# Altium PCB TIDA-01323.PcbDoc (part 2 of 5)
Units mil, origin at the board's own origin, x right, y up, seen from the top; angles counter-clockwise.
Board outline 2467 x 6135 mil, 6 copper layers (Layer 1 - Top Layer, Layer 2 - GND, Layer 3 - Sensitive, Layer 4 - GND, Layer 5 - PWR, Layer 6 - Bottom Layer), stack 62.468 mil thick; 310 components, 202 nets, 881 pads, 527 vias.
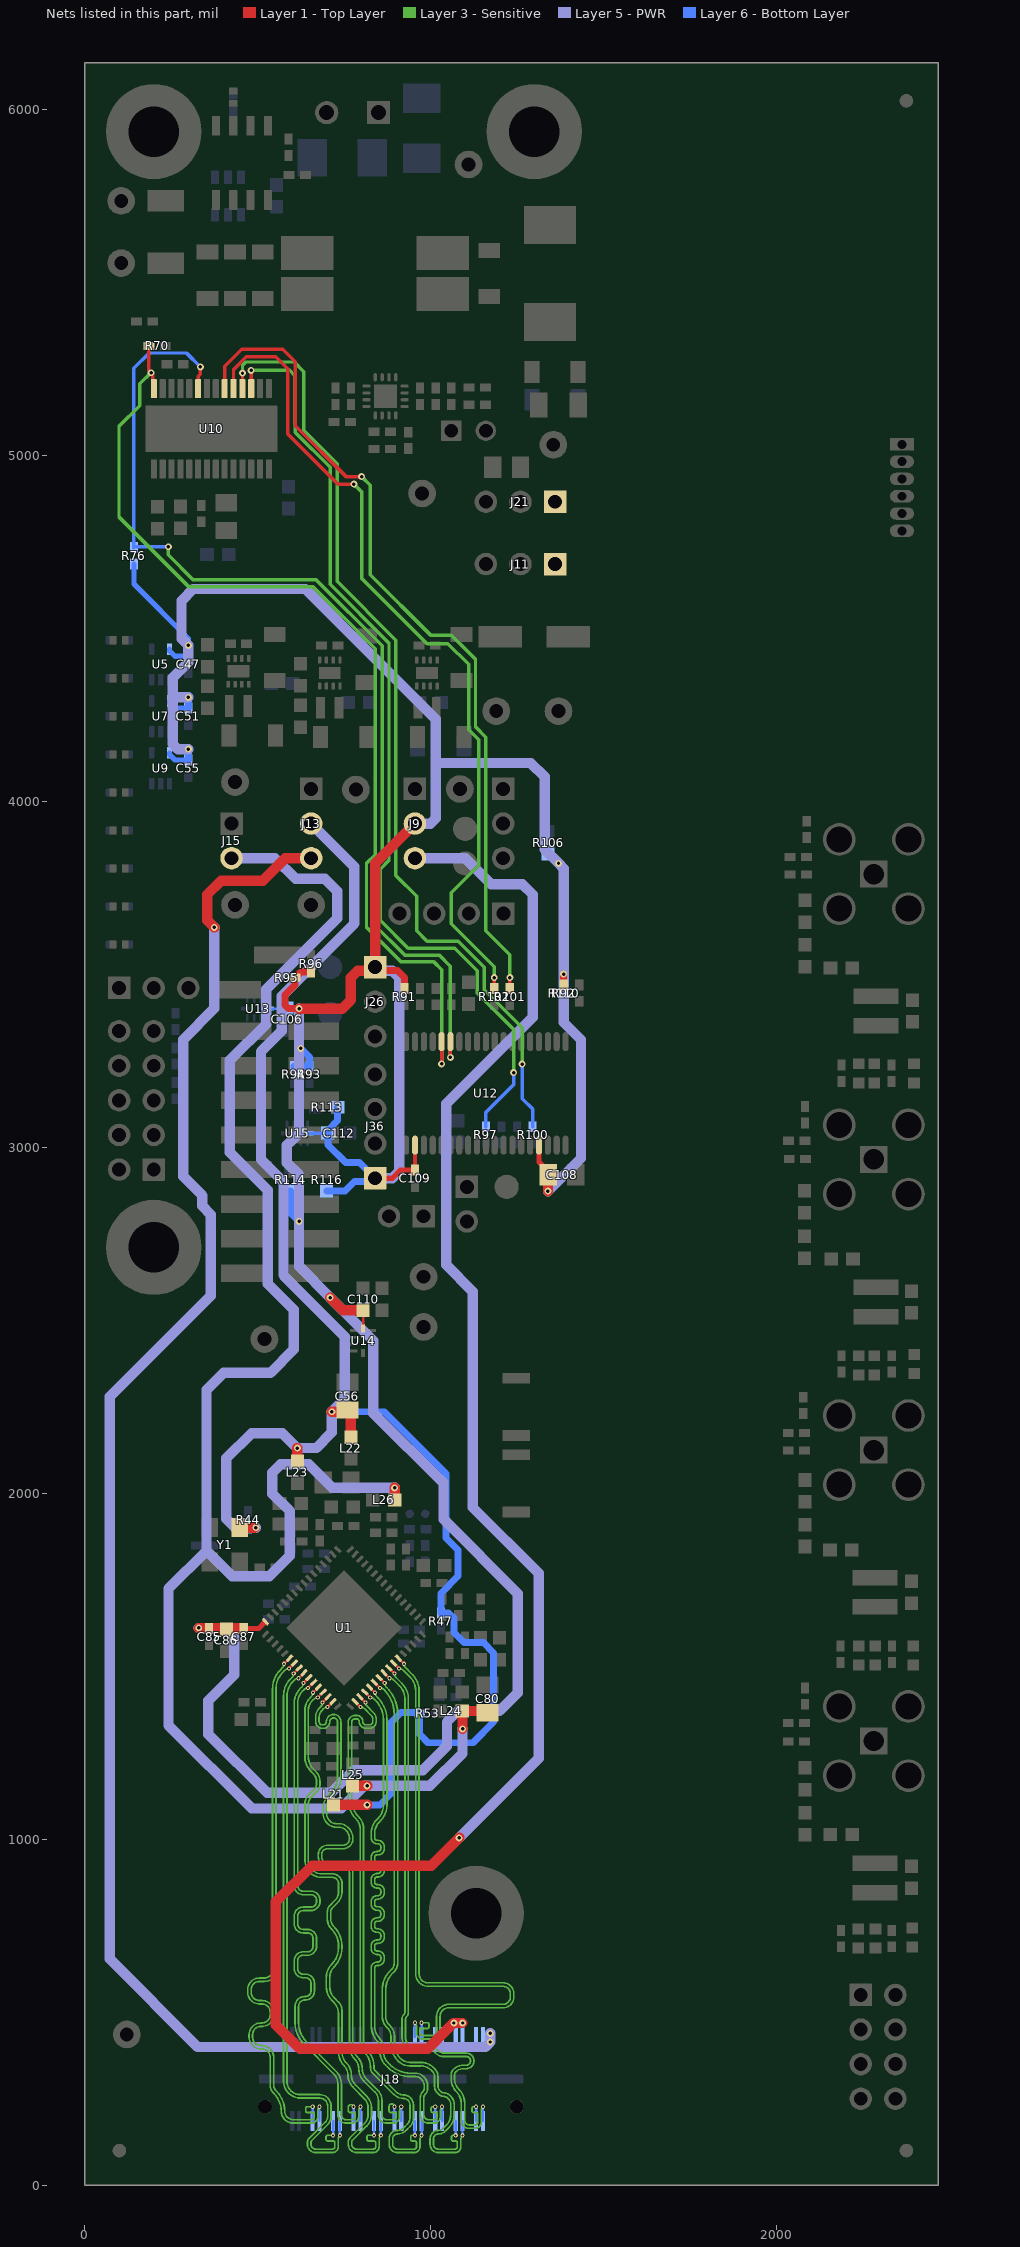
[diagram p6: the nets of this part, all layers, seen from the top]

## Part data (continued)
D6: "LED, Yellow/green, SMD", Color=yellow/green, Manufacturer=Rohm, Supplier Part Number 1=511-1591-1-ND, Value1=W, Value2=2.2V
D7 D12: "LED, Yellow, SMD", Color=yellow, Manufacturer=Rohm, Supplier Part Number 1=511-1595-1-ND, Value1=W, Value2=2.1V
D9: "LED, Red, SMD", Color=Red, Manufacturer=Rohm, Power_TotalModule=0.05, Supplier Part Number 1=511-1594-1-ND, Value1=0.05W, Value2=2V
D10: "LED, Blue, SMD", Color=Blue, Manufacturer=Rohm, Power_TotalModule=0.033, Supplier Part Number 1=846-1112-1-ND, Value1=0.033W, Value2=2.9V
D14: "LED, Orange, SMD", Color=orange, Manufacturer=Rohm, Supplier Part Number 1=511-1590-1-ND, Value1=W, Value2=2.1V
FID1 FID2 FID3 FID4 FID5 FID6: "Fiducial mark.  There is nothing to buy or mount.", Manufacturer=N/A
H1 H2 H3 H4: "MACHINE SCREW PAN SLOTTED M3", Manufacturer="Keystone Electronics", Supplier Part Number 1=36-29341-ND
H9 H10 H11 H12: "HEX STANDOFF M3 NYLON 40MM", Color=Natural, Manufacturer="Essentra Components", Supplier Part Number 1=RPC1486-ND
J1 J2 J3 J4: "RIGHT ANGLE PLUG FOR PCB", Manufacturer=Rosenberger
J5: "Conn Term Block, 2POS, 3.81mm, TH", Manufacturer="Phoenix Contact", Supplier Part Number 1=277-1947-ND
J8: "Header, 100mil, 2x1, Tin, TH", Manufacturer="Sullins Connector Solutions", Supplier Part Number 1=S1012E-02-ND
J9 J10 J11 J13 J21 J26 J35: "Header, 100mil, 3x1, Gold, TH", Manufacturer=Samtec, Supplier Part Number 1=SAM1029-03-ND
J15 J29 J30: "Header, 100mil, 2x1, Gold, TH", Manufacturer=Samtec, Supplier Part Number 1=SAM1029-02-ND
J17: "Header, 100mil, 4x2, Gold, TH", Color=Black, Current_A=6.3, Manufacturer=Samtec, Supplier Part Number 1=SAM1028-04-ND, Voltage_V=550
J18: library part QTH-020-01-L-D-DP-A, "Male, Differential, 0.5mm, 10 pair x2, Gold, SMT", Manufacturer=Samtec, Supplier Part Number 1=QTH-020-04-L-D-DP-A-ND
J20: "Header, 100mil, 5x2, Gold, TH", Manufacturer=Samtec, Supplier Part Number 1=SAM1028-05-ND
J27: "Header, 2.54mm, 8x2, Gold, SMT", Color=Black, Current_A=4.9, Manufacturer=Samtec, Supplier Part Number 1=SAM8884-ND, Voltage_V=475
J28: "Header, 100mil, 2x1, Gold with Tin Tail, SMT", Color=Black, Current_A=5.4, Manufacturer=Samtec, Supplier Part Number 1=TSM-102-01-L-SV-ND, Voltage_V=475
J31: "Receptacle, 50mil, 6x1, Gold, R/A, TH", Manufacturer=Mill-Max
J32 J36: "Header, 100mil, 4x1, Gold, TH", Manufacturer=Samtec, Supplier Part Number 1=SAM1029-04-ND
L1 L2 L9 L10: "Ferrite Bead, 1000 ohm @ 100 MHz, 0.4 A, 0603", Manufacturer=MuRata, Supplier Part Number 1=490-1015-1-ND, Value1="0.5 ohm", Value2=0.4A
L3 L5 L7 L8 L11 L13 L15 L16 L27 L28 L29 L30: "Ferrite Bead, 1500 ohm @ 100 MHz, 0.5 A, 0603", Manufacturer=MuRata, Supplier Part Number 1=490-5216-1-ND, Value1="0.5 ohm", Value2=0.5A
L4 L6 L12 L14: "Inductor, Wirewound, Ferrite, 10 µH, 0.5 A, 0.57 ohm, SMD", Manufacturer=MuRata, Supplier Part Number 1=490-5123-1-ND, Value1="0.57 ohm", Value2=0.5A, ValueDisplayed=10µH
L17: "Ind, Dual, 2.2uH, 20%, 6.23A, 8.05mE, Shielded, SMD", Manufacturer=Coiltronics, Supplier Part Number 1=513-1307-1-ND, Tolerance_%=20, ValueDisplayed=2.2µH
L18 L19 L20: library part VLS201610ET-2R2M, "Inductor, Shielded, Ferrite, 2.2 µH, 1.45 A, 0.170 ohm, SMD", Manufacturer=TDK, Value1="0.170 ohm", Value2=1.45A, ValueDisplayed=2.2µH
L21: "Ferrite Bead, 120 ohm @ 100 MHz, 3 A, 0603", Manufacturer=MuRata, Supplier Part Number 1=490-3996-1-ND, Value1="0.025 ohm", Value2=3A
L22 L23 L24 L25 L26: library part BLM18SG331TN1D, "1.5A Ferrite Bead, 330 ohm @ 100MHz, SMD", Manufacturer=MuRata, Supplier Part Number 1=490-3996-1-ND, Value1="25 milliohm", Value2=3A
Logo2: library part Pb-Free
Q1: "MOSFET, N-CH, 60 V, 12 A, SOIC-8", Alternate Manufacturer=None, Manufacturer=Vishay-Siliconix, Supplier Part Number 1=SQ4850EY-T1-GE3-ND, Value1="0.031 ohm", Value2="20 nC"
R2 R4 R10 R12: "RES, 4.02 k, 1%, 0.1 W, 0603", Manufacturer=Vishay-Dale, Power_W=0.1, Supplier Part Number 1=541-4.02KHCT-ND, TempCo="100 ppm/C", Tolerance_%=1, Value1=1%, Value2=0.1W, Value_Code=4k02, ValueDisplayed=4.02k
R5 R6 R13 R14: "RES, 49.9, 1%, 0.063 W, 0402", Manufacturer=Vishay-Dale, Power_W=0.063, Supplier Part Number 1=541-49.9LCT-ND, TempCo="100 ppm/C", Tolerance_%=1, Value1=1%, Value2=0.063W, Value_Code=49R9, ValueDisplayed=49.9
R17: "RES, 0, 5%, 0.75 W, 2010", Manufacturer=Vishay-Dale, Power_W=0.75, Supplier Part Number 1=541-0.0WCT-ND, TempCo=ppm/C, Tolerance_%=5, Value1=5%, Value2=0.75W, Value_Code=0000, ValueDisplayed=0
R18 R22 R76: "RES, 2.2 k, 5%, 0.063 W, 0402", Manufacturer=Vishay-Dale, Power_W=0.063, Supplier Part Number 1=541-2.2KJCT-ND, TempCo="200 ppm/C", Tolerance_%=5, Value1=5%, Value2=0.063W, Value_Code=2k20, ValueDisplayed=2.2k
R19: "Res, Chip, 0E, 1/8W, JUMP, 0805", Manufacturer=Vishay-Dale, Power_W=0.125, Supplier Part Number 1=541-0.0ACT-ND, TempCo="200 ppm/C", Tolerance_%=5, Value1=5%, Value2=0.125W, Value_Code=0000
R20: "Res, Chip, 100K, 1/4W, 5%, 1206", Manufacturer=Vishay-Dale, PART Name=SCH_LIB\RES, Power_W=0.25, Supplier Part Number 1=541-100KECT-ND, TempCo="200 ppm/C", Tolerance_%=5, Value1=5%, Value2=0.25W, Value_Code=100k
R21 R91 R92 R110: "Res, Chip, 10K, 1/16W, 5%, 0402", Manufacturer=Vishay-Dale, PART Name=SCH_LIB\RES, Power_W=0.063, Supplier Part Number 1=71-CRCW0402J-10K-E3, TempCo="200 ppm/C", Tolerance_%=5, Value1=5%, Value2=0.063W, Value_Code=10k0
R23: "RES, 2.32k ohm, 1%, 0.063W, 0402", Manufacturer=Vishay-Dale, Power_W=0.063, Supplier Part Number 1=541-2.32KLCT-ND, TempCo="100 ppm/C", Tolerance_%=1, Value1=1%, Value2=0.063W, Value_Code=2k32
R24: "RES, 49.9 ohm, 1%, 0.063W, 0402", Manufacturer=Vishay-Dale, Power_W=0.063, Supplier Part Number 1=541-49.9LCT-ND, TempCo="100 ppm/C", Tolerance_%=1, Value1=1%, Value2=0.063W, Value_Code=49R9
R25: "RES, 18.2k ohm, 1%, 0.063W, 0402", Manufacturer=Vishay-Dale, Power_W=0.063, Supplier Part Number 1=541-18.2KLCT-ND, TempCo="100 ppm/C", Tolerance_%=1, Value1=1%, Value2=0.063W, Value_Code=18k2
R26: "RES, 75.0 k, 1%, 0.063 W, 0402", Manufacturer=Vishay-Dale, Power_W=0.063, Supplier Part Number 1=541-75.0KLCT-ND, TempCo="100 ppm/C", Tolerance_%=1, Value1=1%, Value2=0.063W, Value_Code=75k0, ValueDisplayed=75.0k
R27: "RES, 86.6 k, 1%, 0.063 W, 0402", Manufacturer=Vishay-Dale, Power_W=0.063, Supplier Part Number 1=541-86.6KLCT-ND, TempCo="100 ppm/C", Tolerance_%=1, Value1=1%, Value2=0.063W, Value_Code=86k6, ValueDisplayed=86.6k
R28: "RES, 10.0 k, 1%, 0.063 W, 0402", Manufacturer=Vishay-Dale, Power_W=0.063, Supplier Part Number 1=541-10.0KLCT-ND, TempCo="100 ppm/C", Tolerance_%=1, Value1=1%, Value2=0.063W, Value_Code=10k0, ValueDisplayed=10.0k
R29 R34 R37 R39 R42: "RES, 100 k, 1%, 0.1 W, 0603", Manufacturer=Vishay-Dale, Power_W=0.1, Supplier Part Number 1=541-100KHCT-ND, TempCo="100 ppm/C", Tolerance_%=1, Value1=1%, Value2=0.1W, Value_Code=100k
R31 R36 R41: "RES, 10 k, 5%, 0.063 W, 0402", Manufacturer=Vishay-Dale, Power_W=0.063, Supplier Part Number 1=541-10KJCT-ND, TempCo="200 ppm/C", Tolerance_%=5, Value1=5%, Value2=0.063W, Value_Code=10k0, ValueDisplayed=10k
R33: "RES, 360, 5%, 0.063 W, 0402", Manufacturer=Vishay-Dale, Power_W=0.063, Supplier Part Number 1=541-360JCT-ND, TempCo="200 ppm/C", Tolerance_%=5, Value1=5%, Value2=0.063W, Value_Code=360R, ValueDisplayed=360
R35: "RES, 124 k, 1%, 0.1 W, 0603", Manufacturer=Vishay-Dale, Power_W=0.1, Supplier Part Number 1=541-124KHCT-ND, TempCo="100 ppm/C", Tolerance_%=1, Value1=1%, Value2=0.1W, Value_Code=124k
R38: "RES, 470, 5%, 0.063 W, 0402", Manufacturer=Vishay-Dale, Power_W=0.063, Supplier Part Number 1=541-470JCT-ND, TempCo="200 ppm/C", Tolerance_%=5, Value1=5%, Value2=0.063W, Value_Code=470R, ValueDisplayed=470
R40: "RES, 37.4 k, 1%, 0.1 W, 0603", Manufacturer=Vishay-Dale, Power_W=0.1, Supplier Part Number 1=541-37.4KHCT-ND, TempCo="100 ppm/C", Tolerance_%=1, Value1=1%, Value2=0.1W, Value_Code=37k4, ValueDisplayed=37.4k
R43 R59 R111 R115: "RES, 220, 5%, 0.063 W, 0402", Manufacturer=Vishay-Dale, Power_W=0.063, Supplier Part Number 1=541-220JCT-ND, TempCo="200 ppm/C", Tolerance_%=5, Value1=5%, Value2=0.063W, Value_Code=220R, ValueDisplayed=220
R44 R54: "RES, 10k ohm, 5%, 0.063W, 0402", Manufacturer=Vishay-Dale, Power_W=0.063, Supplier Part Number 1=71-CRCW0402J-10K-E3, TempCo="200 ppm/C", Tolerance_%=5, Value1=5%, Value2=0.063W, Value_Code=10k0
R45 R46 R56 R57 R58: "RES, 0, 5%, 0.063 W, 0402", Manufacturer=Panasonic, Power_W=0.063, Supplier Part Number 1=P0.0JCT-ND, TempCo="600 ppm/C", Tolerance_%=5, Value1=5%, Value2=0.063W, Value_Code=0000, ValueDisplayed=0
R47: "RES, 13.3 k, 1%, 0.063 W, 0402", Manufacturer=Vishay-Dale, Power_W=0.063, Supplier Part Number 1=541-13.3KLCT-ND, TempCo="100 ppm/C", Tolerance_%=1, Value1=1%, Value2=0.063W, Value_Code=13k3, ValueDisplayed=13.3k
R48: "RES, 40.2 k, 1%, 0.063 W, 0402", Manufacturer=Vishay-Dale, Power_W=0.063, Supplier Part Number 1=541-40.2KLCT-ND, TempCo="100 ppm/C", Tolerance_%=1, Value1=1%, Value2=0.063W, Value_Code=40k2, ValueDisplayed=40.2k
R49: "RES, 4.12 k, 1%, 0.063 W, 0402", Manufacturer=Vishay-Dale, Power_W=0.063, Supplier Part Number 1=541-4.12KLCT-ND, TempCo="100 ppm/C", Tolerance_%=1, Value1=1%, Value2=0.063W, Value_Code=4k12, ValueDisplayed=4.12k
R50: "RES, 100 ohm, 1%, 0.063W, 0402", Manufacturer=Vishay-Dale, Power_W=0.063, Supplier Part Number 1=541-100LCT-ND, TempCo="100 ppm/C", Tolerance_%=1, Value1=1%, Value2=0.063W, Value_Code=100R
R51: "RES, 4.99 k, 1%, 0.063 W, 0402", Manufacturer=Vishay-Dale, Power_W=0.063, Supplier Part Number 1=541-4.99KLCT-ND, TempCo="100 ppm/C", Tolerance_%=1, Value1=1%, Value2=0.063W, Value_Code=4k99, ValueDisplayed=4.99k
R52: "RES, 0 ohm, 5%, 0.063W, 0402", Manufacturer=Panasonic, Power_W=0.063, Supplier Part Number 1=P0.0JCT-ND, TempCo="600 ppm/C", Tolerance_%=5, Value1=5%, Value2=0.063W, Value_Code=0000
R53: "RES, 82.5 k, 1%, 0.063 W, AEC-Q200 Grade 0, 0402", Manufacturer=Vishay-Dale, Power_W=0.063, Supplier Part Number 1=541-82.5KLCT-ND, TempCo="100 ppm/C", Tolerance_%=1, Value1=1%, Value2=0.063W, Value_Code=82k5, ValueDisplayed=82.5k
R55: "RES, 102 k, 1%, 0.063 W, 0402", Manufacturer=Vishay-Dale, Power_W=0.063, Supplier Part Number 1=541-102KLCT-ND, TempCo="100 ppm/C", Tolerance_%=1, Value1=1%, Value2=0.063W, Value_Code=102k
R64 R66 R78 R80 R103 R106: "RES, 0 ohm, 5%, 0.1W, 0603", Manufacturer=Vishay-Dale, Power_W=0.1, Supplier Part Number 1=541-0.0GCT-ND, TempCo="200 ppm/C", Tolerance_%=5, Value1=5%, Value2=0.1W, Value_Code=0000
R70 R93 R94 R95 R96: "Res, Chip, 4.7K, 1/16W, 5%, 0402", Manufacturer=Vishay-Dale, PART Name=SCH_LIB\RES, Power_W=0.063, Supplier Part Number 1=71-CRCW0402J-4.7K-E3, TempCo="200 ppm/C", Tolerance_%=5, Value1=5%, Value2=0.063W, Value_Code=4k70
R71: "RES, 1.30 k, 1%, 0.063 W, 0402", Manufacturer=Vishay-Dale, Power_W=0.063, Supplier Part Number 1=541-1.30KLCT-ND, TempCo="100 ppm/C", Tolerance_%=1, Value1=1%, Value2=0.063W, Value_Code=1k30, ValueDisplayed=1.30k
R74: "RES, 1.2 k, 5%, 0.063 W, 0402", Manufacturer=Vishay-Dale, Power_W=0.063, Supplier Part Number 1=541-1.2KJCT-ND, TempCo="200 ppm/C", Tolerance_%=5, Value1=5%, Value2=0.063W, Value_Code=1k20, ValueDisplayed=1.2k
R97 R98 R99 R100 R101 R102: "RES, 0 ohm, 5%, 0.063W, 0402", Manufacturer=Vishay-Dale, Power_W=0.063, Supplier Part Number 1=541-0.0JCT-ND, TempCo="200 ppm/C", Tolerance_%=5, Value1=5%, Value2=0.063W, Value_Code=0000
R104 R109 R113 R114 R116: "RES, 4.7k ohm, 5%, 0.1W, 0603", Manufacturer=Vishay-Dale, Power_W=0.1, Supplier Part Number 1=71-CRCW0603J-4.7K-E3, TempCo="200 ppm/C", Tolerance_%=5, Value1=5%, Value2=0.1W, Value_Code=4k70
R105 R107 R108: "RES, 200, 5%, 0.063 W, 0402", Manufacturer=Vishay-Dale, Power_W=0.063, Supplier Part Number 1=541-200JCT-ND, TempCo="200 ppm/C", Tolerance_%=5, Value1=5%, Value2=0.063W, Value_Code=200R, ValueDisplayed=200
R112 R117: "RES, 487 ohm, 1%, 0.063W, 0402", Alternate Manufacturer=Any, Alternate PartNumber=Equivalent, Manufacturer=Vishay-Dale, Power_W=0.063, Supplier Part Number 1=541-487LCT-ND, TempCo="100 ppm/C", Tolerance_%=1, Value1=1%, Value2=0.063W, Value_Code=487R
S1 S2: "Switch, Tactile, 12v, 50mA, Vertical, SMD", Alternate Manufacturer=Any, Alternate PartNumber=Equivalent, CurrentRating_mA=50, Manufacturer=Alps, Supplier Part Number 1=688-SKRKAE
TP5 TP6 TP7 TP8 TP9 TP10 TP21 TP22 TP23 TP24: "Test Point, Miniature, Red, TH", Manufacturer=Keystone, Supplier Part Number 1=5000K-ND
TP11 TP12 TP14 TP15 TP16 TP18: "Test Point, Miniature, Black, TH", Manufacturer=Keystone, Supplier Part Number 1=5001K-ND
TP19 TP20: "Test Point, O.025\"", Manufacturer=STD
TP25 TP26 TP27 TP28 TP29: library part PogoPad, "Pad for Pogo Pin Connector"
U1: "FPD-Link III Camera Hub Deserializer, RGC0064G", Alternate Manufacturer="Texas Instruments", Alternate PartNumber=DS90UB960TRGCTQ1
U2: "Low Iq Always ON Smart Diode Controller, DDC0006A (SOT-23-T-6)", Alternate Manufacturer="Texas Instruments"
U3: "Integrated 5-A 40-V Wide Input Range Boost/SEPIC/Flyback DC-DC Regulator, RTE0016C", Alternate Manufacturer="Texas Instruments", Alternate PartNumber=TPS55340QRTETQ1
U4: "3V-17V 1A Automotive Step-Down Converters in 2x2SON, DSG0008A (WSON-8)", Alternate Manufacturer="Texas Instruments", Alternate PartNumber=TPS62162QDSGTQ1
U5 U7 U9: "Single Bus Buffer Gate With 3-State Output, DCK0005A", Alternate Manufacturer="Texas Instruments", Alternate PartNumber=SN74LVC1G125DCKT
U6 U8: "3-V to 17-V 1-A Step-Down Converter with DCS-Control™, DSG0008A", Alternate Manufacturer="Texas Instruments", Alternate PartNumber=TPS62160QDSGTQ1
U10: "40-V/160-mO Quad Channels Smart High-Side Switch, PWP0028C (TSSOP-28)", Alternate Manufacturer="Texas Instruments"
U12: "16 MHz Mixed Signal Microcontroller with 32 KB Flash, 1024 B SARM and 32 GPIOs, -40 to 105 degC, 38-pin SOP (DA)", Alternate Manufacturer="Texas Instruments", Alternate PartNumber=Equivalent, Frequency(MHz)=16, Pin/Package="38TSSOP, 40VQFN", Temp Sensor=Yes
U13: "IC, TS3USB221A-Q1, Dual USB Switch, UQFN-10", Alternate Manufacturer=None, Alternate PartNumber=Equivalent, Manufacturer="Texas Instruments", Supplier Part Number 1=296-27719-2-ND
U14 U15: "Automotive Catalog ESD Protected, High-Speed USB 2.0 (480-Mbps) 1:2 Multiplexer / Demultiplexer Switch, 16 ohm RON, 2.5 to 3.3V, -40 to 125 degC, 10-Pin UQFN (RSE), Green (RoHS & no Sb/Br)", Alternate Manufacturer=None, Alternate PartNumber=Equivalent, Manufacturer="Texas Instruments", Supplier Part Number 1=296-27719-2-ND
Y1: "XO, 25.000MHz, 2.5V, SMD", Frequency=25MHz, Frequency Stability=±50ppm, Manufacturer="TXC Corporation"
ZZ2 ZZ3 ZZ4: library part AssemblyNote, Alternate Manufacturer=-

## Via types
v1: diameter 20, hole 10, Layer 1 - Top Layer to Layer 6 - Bottom Layer, tented both sides, 397 vias
v2: diameter 19.68, hole 7.87, Layer 1 - Top Layer to Layer 6 - Bottom Layer, tented both sides, 64 vias
v3: diameter 12, hole 6, Layer 1 - Top Layer to Layer 6 - Bottom Layer, tented both sides, 58 vias
v4: diameter 30, hole 15, Layer 1 - Top Layer to Layer 6 - Bottom Layer, tented both sides, 8 vias

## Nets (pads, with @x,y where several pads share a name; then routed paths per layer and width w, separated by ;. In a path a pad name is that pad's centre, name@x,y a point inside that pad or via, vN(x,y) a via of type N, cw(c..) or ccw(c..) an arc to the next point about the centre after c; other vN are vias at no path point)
1V1: C80.1 J15.2 L24.1 L25.1 L26.1 | length 5429.5
  Layer 1 - Top Layer w30: L25.1@774.38,1154.37 v1(816.38,1154.37) ; L26.1@895.88,1980.87 v1(895.88,2015.87) ; v1(1092,1319) 1092,1369.74 L24.1@1090.88,1370.87 1159.38,1370.87 C80.1@1164.38,1365.87
  Layer 5 - PWR w30: J15.2@424.38,3835.87 549.38,3835.87 609.38,3775.87 694.38,3775.87 729.38,3740.87 729.38,3661.87 524.38,3456.87 524.38,3356.38 419.38,3251.38 419.38,2985.87 529.38,2875.87 529.38,2605.87 604.03,2531.22 604.03,2416.03 537,2349 401.13,2349 352,2299.87 352,1834 ; v1(895.88,2015.87) 715.13,2015.87 647,2084 567,2084 542,2059 542,1999 592,1949 592,1819 533,1760 426,1760 352,1834 ; v1(1092,1319) 1092,1249 997.37,1154.37 v1(816.38,1154.37) 807.37,1154.37 742,1089 482,1089 242,1329 242,1724 352,1834
1V8: C56.1 J13.2 L21.1 L22.1 L23.1 R44.1 R47.2 R53.2 Y1.4 | length 4962.6
  Layer 1 - Top Layer w30: Y1.4@453,1906.18 Y1.4@447.69,1900.87 448.69,1899.87 449.69,1900.87 v1@490.38,1900.87 ; L23.1@614.38,2092.37 v1(614.38,2130.87) ; v1(714.38,2235.87) C56.1@759.38,2235.87 ; L21.1@719.38,1099.37 v1(816.38,1099.37) ; L22.1@769.38,2162.37 C56.1@769.38,2230.87
  Layer 5 - PWR w30: v1(494.38,1900.87) 435.13,1900.87 409.38,1926.62 409.38,2101.38 482,2174 571.25,2174 v1(614.38,2130.87) 668.87,2130.87 714.38,2176.38 v1(714.38,2235.87) 752,2273.49 752,2453.25 574.38,2630.87 574.38,2900.87 509.38,2965.87 509.38,3276.38 569.38,3336.38 569.38,3436.87 779.38,3646.87 779.38,3810.87 J13.2@654.38,3935.87
  Layer 6 - Bottom Layer w20: R44.1@472,1899.82 473.04,1900.87 v1(494.38,1900.87) ; v1(714.38,2235.87) 865.13,2235.87 1044.38,2056.62 1044.38,1870.87 1079.38,1835.87 1079.38,1760.87 1029.38,1710.87 R47.2@1029.38,1654.49 1051.51,1654.49 1067,1639 1067,1597.75 1095.75,1569 1152,1569 1182,1539 1182,1339 1122,1279 992,1279 968.38,1302.62 R53.2@968.38,1364 ; v1(816.38,1099.37) 852.88,1099.37 884.38,1130.87 884.38,1335.87 914.38,1365.87 R53.2@968.38,1365.87
3V3: C47.1 C51.1 C55.1 C85.1 C86.1 C87.1 C106.1 C108.1 C109.1 C110.1 C112.1 J9.2 J26.1 J36.1 R76.1 R91.2 R92.2 R93.2 R94.2 R95.2 R96.2 R106.2 R110.2 R113.2 R114.2 R116.2 U1.16 U5.5 U7.5 U9.5 U12.2 U12.16 U13.10 U14.10 U15.10 | length 11219.3
  Layer 1 - Top Layer w7: U14.10@804.38,2476.3 C110.1@804.38,2529.37
  Layer 1 - Top Layer w12: C109.1@954.65,2935.87 U12.2@954.65,3006.26
  Layer 1 - Top Layer w15: C87.1@459.38,1609.49 503.02,1609.49 U1.16@519.89,1626.36 ; J36.1@839.38,2910.87 889.38,2910.87 913,2934.49 C109.1@954.38,2934.49 ; U12.16@1312.92,3006.26 1312.92,2957.33 1339.38,2930.87 C108.1@1339.38,2920.87
  Layer 1 - Top Layer w20: v1(619.38,3400.87) 589.38,3400.87 579.38,3410.87 579.38,3440.87 608,3469.49 R95.2@608,3490.87 624.38,3507.25 R96.2@654.38,3507.25 ; J26.1@839.38,3510.87 904.38,3510.87 923.88,3491.37 R91.2@923.88,3459.49 ; R110.2@1384.38,3469.49 v1(1384.38,3500.87)
  Layer 1 - Top Layer w30: v1@329.76,1609.87 C85.1@358.38,1609.87 ; C85.1@359.38,1609.49 C87.1@454.38,1609.49 ; v1(619.38,3400.87) 744.38,3400.87 769.38,3425.87 769.38,3490.87 789.38,3510.87 839.38,3510.87 J26.1@839.38,3520.87 839.38,3820.87 J9.2@954.38,3935.87 ; v1(709.38,2565.87) 745.88,2529.37 C110.1@804.38,2529.37 ; v1(1338.88,2873.37) 1338.88,2920.37 C108.1@1339.38,2920.87
  Layer 5 - PWR w30: v1(299.38,4150.87) 269.38,4150.87 254.38,4165.87 254.38,4300.87 ; v1(299.38,4300.87) 254.38,4300.87 ; v1(329.38,1610.87) 405.88,1610.87 432,1584.74 432,1475.87 357,1400.87 357,1304 527,1134 712,1134 777,1199 977,1199 1047,1269 1047,1339 1078.87,1370.87 1198.87,1370.87 1252,1424 1252,1709.34 1037,1924.34 1037,2029 834.38,2231.62 834.38,2440.87 v1(709.38,2565.87) 619.38,2655.87 v1(619.38,2785.87) 619.38,2920.87 584.38,2955.87 584.38,3005.87 619.38,3040.87 v1(619.38,3400.87) ; J36.1@839.38,2910.87 889.38,2910.87 909.38,2930.87 909.38,3490.87 889.38,3510.87 J26.1@839.38,3510.87 ; J9.2@954.38,3935.87 999.38,3935.87 1014.38,3950.87 1014.38,4110.87 ; v1(1338.88,2873.37) 1434.38,2968.87 1434.38,3310.87 1384.38,3360.87 v1(1384.38,3500.87) 1384.38,3805.87 v1(1369.38,3820.87) 1329.38,3860.87 1329.38,4070.87 1289.38,4110.87 1014.38,4110.87 ; 254.38,4300.87 254.38,4357.25 299.38,4402.25 v1(299.38,4450.87) 279.79,4470.46 279.79,4579.79 314,4614 637.85,4614 1014.38,4237.47 1014.38,4110.87
  Layer 6 - Bottom Layer w7: U13.10@534.81,3400.87 582.88,3400.87 C106.1@584.38,3402.37
  Layer 6 - Bottom Layer w10: U15.10@649.81,3040.87 C112.1@702.88,3040.87
  Layer 6 - Bottom Layer w15: R76.1@142,4686.38 142,4628 299.38,4470.62 v1(299.38,4450.87) ; U9.5@244.97,4140.16 244.97,4135.28 260.76,4119.49 C55.1@299.38,4119.49 ; U7.5@244.97,4290.16 244.97,4285.28 260.76,4269.49 C51.1@299.38,4269.49 ; U5.5@244.97,4440.16 244.97,4435.28 260.76,4419.49 C47.1@299.38,4419.49
  Layer 6 - Bottom Layer w20: C55.1@299.38,4119.49 v1(299.38,4150.87) ; C51.1@299.38,4269.49 v1(299.38,4300.87) ; C47.1@299.38,4419.49 v1(299.38,4450.87) ; C106.1@584.38,3402.37 585.88,3400.87 v1(619.38,3400.87) ; R114.2@594.38,2874.37 594.38,2810.87 v1(619.38,2785.87) ; R94.2@604.38,3234.49 R93.2@649.38,3234.49 649.38,3260.87 v1(624.38,3285.87) ; R116.2@699.38,2874.37 752.88,2874.37 779.38,2900.87 829.38,2900.87 J36.1@839.38,2910.87 794.38,2955.87 754.38,2955.87 702.88,3007.37 C112.1@702.88,3040.87 702.88,3049.37 730.88,3077.37 R113.2@730.88,3115.87 ; R106.2@1339.38,3849.37 1367.88,3820.87 v1(1369.38,3820.87) ; R92.2@1384.38,3469.49 v1(1384.38,3500.87)
CSI0_CLK_N: J18.7 U1.22 | length 1701
  Layer 1 - Top Layer w7: v3(576.1,1507.19) U1.22@592.08,1523.19
  Layer 3 - Sensitive w5: v3(576.1,1507.19) cw(c559.56,1507.2) 571.26,1495.52 564.6,1488.85 ccw(c616.74,1436.71) 543,1436.71 543,623 cw(c519,623) 519,599 505,599 ccw(c505,565) 471,565 471,558 ccw(c505,558) 505,524 512,524 cw(c512,500) 536,500 536,493 cw(c512,493) 512,469 509,469 ccw(c509,435) 475,435 475,428 ccw(c509,428) 509,394 512,394 cw(c512,370) 536,370 536,288.73 ccw(c566.73,288.73) 545,267 546.79,265.21 cw(c495.57,214) 568,214 ccw(c602.36,214) 602.36,179.64 655.07,179.64 ccw(c655.07,198.26) 673.69,198.26 673.69,215.18 cw(c690.22,215.18) v3(678.53,226.87)
  Layer 6 - Bottom Layer w7: J18.7@678.53,185.61 v3(678.53,226.87)
CSI0_CLK_P: J18.5 U1.23 | length 1700.5
  Layer 1 - Top Layer w7: v3(590.02,1493.27) U1.23@606,1509.26
  Layer 3 - Sensitive w5: v3(590.02,1493.27) ccw(c590.02,1476.75) 578.32,1488.44 571.67,1481.78 ccw(c616.74,1436.71) 553,1436.71 553,623 cw(c519,623) 519,589 505,589 ccw(c505,565) 481,565 481,558 ccw(c505,558) 505,534 512,534 cw(c512,500) 546,500 546,493 cw(c512,493) 512,459 509,459 ccw(c509,435) 485,435 485,428 ccw(c509,428) 509,404 512,404 cw(c512,370) 546,370 546,288.73 ccw(c566.73,288.73) 552.07,274.07 553.86,272.28 cw(c495.57,214) 578,214 ccw(c602.36,214) 602.36,189.64 655.07,189.64 ccw(c655.07,198.26) 663.69,198.26 663.69,205.42 ccw(c658.84,205.42) 658.84,210.26 643.44,210.26 ; 642.83,210.26 643.44,210.26 ; v3(658.84,226.87) 642.83,226.87 ccw(c642.83,222.47) 638.44,222.47 638.44,215.26 ccw(c643.44,215.26) 643.44,210.26
  Layer 6 - Bottom Layer w7: J18.5@658.84,185.61 v3(658.84,226.87)
CSI0_D0_N: J18.11 U1.24 | length 1699.3
  Layer 1 - Top Layer w7: v3(603.94,1479.35) U1.24@619.93,1495.34
  Layer 3 - Sensitive w5: v3(603.94,1479.35) cw(c587.41,1479.35) 599.11,1467.67 595.34,1463.91 ccw(c645.95,1413.3) 574.38,1413.3 574.38,300.84 ccw(c623.21,300.84) 623.21,252 679,252 cw(c679,229) 702,229 702,198.26 cw(c679.98,198.26) 695.55,182.69 648.51,135.65 ccw(c660.16,124) 643.68,124 643.68,118.35 ccw(c667.68,118.35) 667.68,94.35 715.68,94.35 ccw(c715.68,111.41) 732.74,111.41 732.74,132.66 cw(c749.27,132.66) v3(737.58,144.35)
  Layer 6 - Bottom Layer w7: v3(737.58,144.35) J18.11@737.58,185.61
CSI0_D0_P: J18.9 U1.25 | length 1698.9
  Layer 1 - Top Layer w7: v3(617.86,1465.43) U1.25@633.85,1481.42
  Layer 3 - Sensitive w5: v3(617.86,1465.43) ccw(c617.86,1448.9) 606.17,1460.59 602.41,1456.84 ccw(c645.95,1413.3) 584.38,1413.3 584.38,300.84 ccw(c623.21,300.84) 623.21,262 679,262 cw(c679,229) 712,229 712,198.26 cw(c679.98,198.26) 702.62,175.62 655.58,128.58 ; 655.57,128.57 ccw(c660.15,124) 653.68,124 653.68,118.35 ccw(c667.68,118.35) 667.68,104.35 715.68,104.35 ccw(c715.68,111.41) 722.74,111.41 722.74,122.9 ccw(c717.9,122.9) 717.9,127.74 702.49,127.74 ; 701.89,127.74 702.49,127.74 ; v3(717.9,144.35) 701.89,144.35 ccw(c701.89,139.95) 697.49,139.95 697.49,132.74 ccw(c702.49,132.74) 702.49,127.74
  Layer 6 - Bottom Layer w7: v3(717.9,144.35) J18.9@717.9,185.61
CSI0_D1_N: J18.15 U1.26 | length 1702.6
  Layer 1 - Top Layer w7: v3(631.78,1451.51) U1.26@647.77,1467.49
  Layer 3 - Sensitive w5: v3(631.78,1451.51) cw(c615.25,1451.51) 626.95,1439.83 623.19,1436.06 ccw(c666.18,1393.07) 605.38,1393.07 605.38,866 ccw(c631.38,866) 631.38,840 654,840 cw(c654,824) 670,824 670,820 cw(c654,820) 654,804 631.38,804 ccw(c631.38,778) 605.38,778 605.38,755.38 ccw(c631.38,755.38) 631.38,729.38 644,729.38 cw(c644,713.38) 660,713.38 660,690.76 cw(c644,690.76) 644,674.76 631.38,674.76 ccw(c631.38,648.76) 605.38,648.76 605.38,626.14 ccw(c631.38,626.14) 631.38,600.14 638,600.14 cw(c638,584.14) 654,584.14 654,561.52 cw(c638,561.52) 638,545.52 636,545.52 ccw(c636,517.52) 608,517.52 608,469.67 ccw(c694.46,469.67) 633.32,408.53 718.68,323.18 cw(c686.53,291.02) 732,291.02 732,202.64 ccw(c755,202.64) 755,179.64 773.18,179.64 ccw(c773.18,198.26) 791.8,198.26 ; 791.8,199.26 791.8,215.18 cw(c808.33,215.18) v3(796.64,226.87)
  Layer 6 - Bottom Layer w7: J18.15@796.64,185.61 v3(796.64,226.87)
CSI0_D1_P: J18.13 U1.27 | length 1700.3
  Layer 1 - Top Layer w7: v3(645.7,1437.59) U1.27@661.7,1453.57
  Layer 3 - Sensitive w5: v3(645.7,1437.59) ccw(c645.71,1421.06) 634.02,1432.75 630.26,1428.99 ccw(c666.18,1393.07) 615.38,1393.07 615.38,866 ccw(c631.38,866) 631.38,850 654,850 cw(c654,824) 680,824 680,820 cw(c654,820) 654,794 631.38,794 ccw(c631.38,778) 615.38,778 615.38,755.38 ccw(c631.38,755.38) 631.38,739.38 644,739.38 cw(c644,713.38) 670,713.38 670,690.76 cw(c644,690.76) 644,664.76 631.38,664.76 ccw(c631.38,648.76) 615.38,648.76 615.38,626.14 ccw(c631.38,626.14) 631.38,610.14 638,610.14 cw(c638,584.14) 664,584.14 664,561.52 cw(c638,561.52) 638,535.52 636,535.52 ccw(c636,517.52) 618,517.52 618,469.67 ccw(c694.47,469.67) 640.4,415.6 725.75,330.25 cw(c686.53,291.02) 742,291.02 742,202.64 ccw(c755,202.64) 755,189.64 773.18,189.64 ccw(c773.18,198.26) 781.8,198.26 781.8,205.42 ccw(c776.96,205.42) 776.96,210.26 767,210.26 cw(c767,215.26) 762,215.26 762,226.82 cw(c768,226.82) 768,232.82 771,232.82 cw(c771,226.87) v3(776.95,226.87)
  Layer 6 - Bottom Layer w7: J18.13@776.95,185.61 v3(776.95,226.87)
CSI0_D2_N: J18.19 U1.28 | length 1701.2
  Layer 1 - Top Layer w7: v3(659.62,1423.68) U1.28@675.62,1439.65
  Layer 3 - Sensitive w5: v3(659.62,1423.68) cw(c643.1,1423.66) 654.8,1411.98 651.03,1408.21 ccw(c686.41,1372.84) 636.38,1372.84 636.38,1237.46 ccw(c693.93,1237.46) 653.24,1196.76 661,1189 cw(c639.27,1167.27) 670,1167.27 670,1159 cw(c651.03,1159) 664.44,1145.59 647.64,1128.78 ccw(c674.81,1101.6) 636.38,1101.6 636.38,938.62 ccw(c685,938.62) 685,890 715.62,890 cw(c715.62,872) 733.62,872 733.62,848.88 cw(c697.12,848.88) 722.93,823.07 709.59,809.73 ccw(c730.31,789) 701,789 701,769.97 ccw(c741.97,769.97) 713,741 cw(c663.22,691.22) 733.62,691.22 733.62,686.37 cw(c666.63,686.37) 714,639 ccw(c752.63,600.37) 698,600.37 698,574 ccw(c753.87,574) 714.36,534.49 719.93,528.93 cw(c686.87,495.87) 733.62,495.87 733.62,384 ccw(c787.18,384) 749.31,346.13 cw(c721.99,318.82) 760.62,318.82 ccw(c811.32,318.82) 775.47,282.97 808.08,250.35 cw(c781.73,224) 819,224 819,204.09 cw(c782.91,204.09) 808.43,178.57 766.69,136.84 ccw(c778.53,125) 761.79,125 761.79,118.35 ccw(c785.79,118.35) 785.79,94.35 833.79,94.35 ccw(c833.79,111.41) 850.85,111.41 850.85,132.66 cw(c867.38,132.66) v3(855.69,144.35)
  Layer 6 - Bottom Layer w7: v3(855.69,144.35) J18.19@855.69,185.61
CSI0_D2_P: J18.17 U1.29 | length 1701.7
  Layer 1 - Top Layer w7: v3@673.55,1409.74 U1.29@689.54,1425.73
  Layer 3 - Sensitive w5: v3@673.55,1409.74 ccw(c673.55,1393.21) 661.86,1404.9 658.1,1401.14 ccw(c686.41,1372.84) 646.38,1372.84 646.38,1238.54 ccw(c696.54,1238.54) 661.07,1203.07 668.07,1196.07 cw(c639.27,1167.27) 680,1167.27 680,1159 cw(c651.03,1159) 671.51,1138.51 654.71,1121.71 ccw(c674.81,1101.6) 646.38,1101.6 646.38,938.62 ccw(c685,938.62) 685,900 715.62,900 cw(c715.62,872) 743.62,872 743.62,848.88 cw(c697.12,848.88) 730,816 716.66,802.66 ccw(c730.31,789) 711,789 711,769.97 ccw(c741.97,769.97) 720.07,748.07 cw(c663.22,691.22) 743.62,691.22 743.62,686.37 cw(c666.63,686.37) 721.07,631.93 ccw(c752.63,600.37) 708,600.37 708,574 ccw(c753.87,574) 721.44,541.56 733.62,529.38 cw(c709.48,505.24) 743.62,505.24 743.62,384 ccw(c787.18,384) 756.38,353.2 cw(c721.99,318.82) 770.62,318.82 ccw(c811.32,318.82) 782.54,290.04 815.16,257.42 cw(c781.73,224) 829,224 829,204.09 cw(c782.91,204.09) 815.5,171.5 773.77,129.77 ccw(c778.53,125) 771.79,125 771.79,118.35 ccw(c785.79,118.35) 785.79,104.35 833.79,104.35 ccw(c833.79,111.41) 840.85,111.41 840.85,122.9 ccw(c836.01,122.9) 836.01,127.74 820.6,127.74 ; 820,127.74 820.6,127.74 ; v3(836.01,144.35) 820,144.35 ccw(c820,139.95) 815.6,139.95 815.6,132.74 ccw(c820.6,132.74) 820.6,127.74
  Layer 6 - Bottom Layer w7: v3(836.01,144.35) J18.17@836.01,185.61
  other v3: 673.54,1409.76
CSI0_D3_N: J18.23 U1.30 | length 1700.2
  Layer 1 - Top Layer w7: v3(687.48,1395.82) U1.30@703.46,1411.8
  Layer 3 - Sensitive w5: v3(687.48,1395.82) cw(c670.96,1395.8) 682.66,1384.12 678.9,1380.35 ccw(c706.66,1352.59) 667.4,1352.59 667.4,1339.85 ccw(c686.4,1339.85) 686.4,1320.85 689.4,1320.85 ccw(c689.4,1339.85) 708.4,1339.85 cw(c719.4,1339.85) 719.4,1350.85 cw(c719.4,1339.85) 730.4,1339.85 730.4,1177 cw(c676.18,1177) 714.52,1138.66 705.93,1130.07 ccw(c746.8,1089.2) 689,1089.2 689,1074.73 ccw(c729.73,1074.73) 700.93,1045.93 ccw(c727.31,1072.31) 727.31,1035 735,1035 cw(c735,1008.44) 753.78,1027.22 756,1025 cw(c734.27,1003.27) 765,1003.27 765,1001 cw(c747,1001) 747,983 702,983 ccw(c702,956) 675,956 675,949 ccw(c702,949) 702,922 747,922 cw(c747,904) 765,904 765,402.18 ccw(c818.56,402.18) 780.69,364.31 cw(c753.37,337) 792,337 ccw(c842.7,337) 806.85,301.15 838.65,269.35 cw(c813.68,244.37) 849,244.37 849,202.64 ccw(c872,202.64) 872,179.64 891.29,179.64 ccw(c891.29,198.26) 909.91,198.26 ; 909.91,199.26 909.91,215.18 cw(c926.44,215.18) v3(914.75,226.87)
  Layer 6 - Bottom Layer w7: J18.23@914.75,185.61 v3(914.75,226.87)
CSI0_D3_P: J18.21 U1.31 | length 1702.3
  Layer 1 - Top Layer w7: v3(701.4,1381.9) U1.31@717.39,1397.88
  Layer 3 - Sensitive w5: v3(701.4,1381.9) ccw(c701.42,1365.34) 689.73,1377.04 685.97,1373.28 ccw(c706.66,1352.59) 677.4,1352.59 677.4,1339.85 ccw(c686.4,1339.85) 686.4,1330.85 689.4,1330.85 ccw(c689.4,1339.85) 698.4,1339.85 cw(c719.4,1339.85) 719.4,1360.85 cw(c719.4,1339.85) 740.4,1339.85 740.4,1177 cw(c676.18,1177) 721.59,1131.59 713,1123 ccw(c746.8,1089.2) 699,1089.2 699,1074.73 ccw(c729.73,1074.73) 708,1053 ccw(c727.31,1072.31) 727.31,1045 735,1045 cw(c735,1008.44) 760.85,1034.29 763.07,1032.07 cw(c734.27,1003.27) 775,1003.27 775,1001 cw(c747,1001) 747,973 702,973 ccw(c702,956) 685,956 685,949 ccw(c702,949) 702,932 747,932 cw(c747,904) 775,904 775,402.18 ccw(c818.56,402.18) 787.76,371.38 cw(c753.37,337) 802,337 ccw(c842.7,337) 813.92,308.22 845.73,276.42 cw(c813.68,244.37) 859,244.37 859,202.64 ccw(c872,202.64) 872,189.64 891.29,189.64 ccw(c891.29,198.26) 899.91,198.26 899.91,205.42 ccw(c895.07,205.42) 895.07,210.26 884.6,210.26 ; 884,210.26 884.6,210.26 ; v3(895.06,226.87) ccw(c887,226.87) 887,234.93 ccw(c887,227.53) 879.6,227.53 879.6,215.26 ccw(c884.6,215.26) 884.6,210.26
  Layer 6 - Bottom Layer w7: J18.21@895.06,185.61 v3(895.06,226.87)
CSI1_CLK_N: J18.27 U1.34 | length 1699.4
  Layer 1 - Top Layer w7: U1.34@781.39,1397.9 v3(797.36,1381.9)
  Layer 3 - Sensitive w5: v3(797.36,1381.9) cw(c797.38,1365.38) 809.07,1377.07 828.92,1357.23 cw(c820.56,1348.87) 832.38,1348.87 832.38,1339.87 cw(c823.38,1339.87) 823.38,1330.87 813.38,1330.87 cw(c813.38,1340.87) 803.38,1340.87 ccw(c786.38,1340.87) 786.38,1357.87 781.38,1357.87 ccw(c781.38,1337.87) 761.38,1337.87 761.38,1270.73 761.38,1113.61 ccw(c838.61,1113.61) 784,1059 cw(c755.03,1030.03) 796,1030.03 796,415.38 ccw(c840.38,415.38) 809,384 cw(c767.96,342.96) 826,342.96 826,339 ccw(c848.07,339) 832.46,323.39 893.44,262.41 ccw(c921,289.97) 921,251 cw(c921,232) 940,232 940,193.9 cw(c916.1,193.9) 933,177 921.74,165.74 cw(c903.9,183.57) 903.9,158.35 ccw(c903.9,134.35) 879.9,134.35 879.9,118.35 ccw(c903.9,118.35) 903.9,94.35 951.9,94.35 ccw(c951.9,111.41) 968.96,111.41 968.96,132.66 cw(c985.5,132.66) v3(973.8,144.35)
  Layer 6 - Bottom Layer w7: v3(973.8,144.35) J18.27@973.8,185.61
CSI1_CLK_P: J18.25 U1.35 | length 1697.4
  Layer 1 - Top Layer w7: U1.35@795.31,1411.82 v3(811.28,1395.82)
  Layer 3 - Sensitive w5: v3(811.28,1395.82) ccw(c827.83,1395.84) 816.13,1384.15 835.99,1364.3 cw(c820.56,1348.87) 842.38,1348.87 842.38,1339.87 cw(c823.38,1339.87) 823.38,1320.87 813.38,1320.87 cw(c813.38,1340.87) 793.38,1340.87 ccw(c786.38,1340.87) 786.38,1347.87 781.38,1347.87 ccw(c781.38,1337.87) 771.38,1337.87 771.38,1113.61 ccw(c838.61,1113.61) 791.07,1066.07 cw(c755.03,1030.03) 806,1030.03 806,415.38 ccw(c840.38,415.38) 816.07,391.07 cw(c767.96,342.96) 836,342.96 836,339 ccw(c848.07,339) 839.54,330.46 900.51,269.49 ccw(c921,289.97) 921,261 cw(c921,232) 950,232 950,193.9 cw(c916.1,193.9) 940.07,169.93 928.81,158.67 cw(c903.9,183.57) 903.9,148.35 ccw(c903.9,134.35) 889.9,134.35 889.9,118.35 ccw(c903.9,118.35) 903.9,104.35 951.9,104.35 ccw(c951.9,111.41) 958.96,111.41 958.96,122.9 ccw(c954.12,122.9) 954.12,127.74 947.07,127.74 cw(c947.07,132.74) 942.07,132.74 942.07,139.95 cw(c946.47,139.95) 946.47,144.35 v3(954.12,144.35)
  Layer 6 - Bottom Layer w7: v3(954.12,144.35) J18.25@954.12,185.61
CSI1_D0_N: J18.31 U1.36 | length 1700
  Layer 1 - Top Layer w7: U1.36@809.23,1425.74 v3@825.22,1409.76
  Layer 3 - Sensitive w5: v3@825.22,1409.76 cw(c825.22,1393.22) 836.91,1404.91 840.67,1401.16 cw(c785.83,1346.32) 863.38,1346.32 863.38,1098 cw(c811.18,1098) 848.09,1061.09 845,1058 ccw(c886.04,1016.96) 828,1016.96 828,1004 ccw(c845,1004) 845,987 847,987 cw(c847,978) 856,978 856,974 cw(c847,974) 847,965 845,965 ccw(c845,948) 828,948 828,940 ccw(c845,940) 845,923 847,923 cw(c847,914) 856,914 856,910 cw(c847,910) 847,901 845,901 ccw(c845,884) 828,884 828,876 ccw(c845,876) 845,859 847,859 cw(c847,850) 856,850 856,846 cw(c847,846) 847,837 845,837 ccw(c845,820) 828,820 828,812 ccw(c845,812) 845,795 847,795 cw(c847,786) 856,786 856,782 cw(c847,782) 847,773 845,773 ccw(c845,756) 828,756 828,748 ccw(c845,748) 845,731 847,731 cw(c847,722) 856,722 856,718 cw(c847,718) 847,709 845,709 ccw(c845,692) 828,692 828,684 ccw(c845,684) 845,667 847,667 cw(c847,658) 856,658 856,654 cw(c847,654) 847,645 845,645 ccw(c845,628) 828,628 828,460.87 ccw(c892.87,460.87) 847,415 cw(c832.51,400.51) 853,400.51 853,387 ccw(c908.87,387) 869.36,347.49 874.93,341.93 ccw(c942.36,409.36) 942.36,314 956.51,314 cw(c956.51,293.51) 971,308 974.64,304.36 cw(c959.27,289) 981,289 981,279.9 cw(c967.1,279.9) 976.93,270.07 ccw(c993.36,253.64) 970.12,253.64 970.12,202.64 ccw(c993.12,202.64) 993.12,179.64 1009.4,179.64 ccw(c1009.4,198.26) 1028.02,198.26 ; 1028.02,199.26 1028.02,215.18 cw(c1044.55,215.18) v3(1032.86,226.87)
  Layer 6 - Bottom Layer w7: J18.31@1032.86,185.61 v3(1032.86,226.87)
  other v3: 825.21,1409.74
CSI1_D0_P: J18.29 U1.37 | length 1699
  Layer 1 - Top Layer w7: U1.37@823.15,1439.66 v3(839.13,1423.66)
  Layer 3 - Sensitive w5: v3(839.13,1423.66) ccw(c855.67,1423.68) 843.97,1411.99 ; 843.98,1411.98 847.74,1408.23 cw(c785.83,1346.32) 873.38,1346.32 873.38,1098 cw(c811.18,1098) 855.16,1054.02 852.07,1050.93 ccw(c886.04,1016.96) 838,1016.96 838,1004 ccw(c845,1004) 845,997 847,997 cw(c847,978) 866,978 866,974 cw(c847,974) 847,955 845,955 ccw(c845,948) 838,948 838,940 ccw(c845,940) 845,933 847,933 cw(c847,914) 866,914 866,910 cw(c847,910) 847,891 845,891 ccw(c845,884) 838,884 838,876 ccw(c845,876) 845,869 847,869 cw(c847,850) 866,850 866,846 cw(c847,846) 847,827 845,827 ccw(c845,820) 838,820 838,812 ccw(c845,812) 845,805 847,805 cw(c847,786) 866,786 866,782 cw(c847,782) 847,763 845,763 ccw(c845,756) 838,756 838,748 ccw(c845,748) 845,741 847,741 cw(c847,722) 866,722 866,718 cw(c847,718) 847,699 845,699 ccw(c845,692) 838,692 838,684 ccw(c845,684) 845,677 847,677 cw(c847,658) 866,658 866,654 cw(c847,654) 847,635 845,635 ccw(c845,628) 838,628 838,460.87 ccw(c892.87,460.87) 854.07,422.07 cw(c832.51,400.51) 863,400.51 863,387 ccw(c908.87,387) 876.44,354.56 882,349 ccw(c942.36,409.36) 942.36,324 956.51,324 cw(c956.51,293.51) 978.07,315.07 981.71,311.44 cw(c959.27,289) 991,289 991,279.9 cw(c967.1,279.9) 984,263 ccw(c993.36,253.64) 980.12,253.64 980.12,202.64 ccw(c993.12,202.64) 993.12,189.64 1009.4,189.64 ccw(c1009.4,198.26) 1018.02,198.26 1018.02,205.42 ccw(c1013.18,205.42) 1013.18,210.26 1006.12,210.26 cw(c1006.12,215.26) 1001.12,215.26 1001.12,222.47 cw(c1005.52,222.47) 1005.52,226.87 v3(1013.17,226.87)
  Layer 6 - Bottom Layer w7: J18.29@1013.17,185.61 v3(1013.17,226.87)
CSI1_D1_N: J18.35 U1.38 | length 1703.2
  Layer 1 - Top Layer w7: U1.38@837.07,1453.58 v3(853.05,1437.59)
  Layer 3 - Sensitive w5: v3(853.05,1437.59) cw(c853.06,1421.06) 864.75,1432.75 865.09,1432.41 cw(c794.38,1361.7) 894.38,1361.7 894.38,641 cw(c871.15,641) 887.58,624.58 881,618 ccw(c931.7,567.3) 860,567.3 860,486.73 ccw(c900.73,486.73) 871.93,457.93 874.49,455.36 cw(c849.13,430) 885,430 885,409 ccw(c955.36,409) 905.61,359.25 905.93,358.93 ccw(c939.56,392.56) 939.56,345 970.62,345 cw(c970.62,300.62) 1002,332 1004.54,329.46 cw(c988.93,313.86) 1011,313.86 1011,286.07 ccw(c1038.07,286.07) 1018.93,266.93 1023.1,262.76 ccw(c1037,276.66) 1037,257 cw(c1037,240.1) 1048.94,252.06 1051,250 cw(c1034.1,233.1) 1058,233.1 1058,204.38 cw(c1013.62,204.38) 1045,173 1036.25,164.25 cw(c1022.01,178.48) 1022.01,158.35 ccw(c1022.01,134.35) 998.01,134.35 998.01,118.35 ccw(c1022.01,118.35) 1022.01,94.35 1070.01,94.35 ccw(c1070.01,111.41) 1087.07,111.41 1087.07,132.66 cw(c1103.61,132.66) v3(1091.91,144.35)
  Layer 6 - Bottom Layer w7: v3(1091.91,144.35) J18.35@1091.91,185.61
CSI1_D1_P: J18.33 U1.39 | length 1701.2
  Layer 1 - Top Layer w7: U1.39@850.99,1467.5 v3(866.97,1451.51)
  Layer 3 - Sensitive w5: v3(866.97,1451.51) ccw(c883.51,1451.51) 871.81,1439.83 872.16,1439.48 cw(c794.38,1361.7) 904.38,1361.7 904.38,641 cw(c871.15,641) 894.65,617.51 888.07,610.93 ccw(c931.7,567.3) 870,567.3 870,486.73 ccw(c900.73,486.73) 879,465 881.56,462.43 cw(c849.13,430) 895,430 895,409 ccw(c955.36,409) 912.68,366.32 913,366 ccw(c939.56,392.56) 939.56,355 970.62,355 cw(c970.62,300.62) 1009.07,339.07 1011.61,336.54 cw(c988.93,313.86) 1021,313.86 1021,286.07 ccw(c1038.07,286.07) 1026,274 1030.17,269.83 ccw(c1037,276.66) 1037,267 cw(c1037,240.1) 1056.02,259.12 1058.07,257.07 cw(c1034.1,233.1) 1068,233.1 1068,204.38 cw(c1013.62,204.38) 1052.07,165.93 1043.32,157.17 cw(c1022.01,178.48) 1022.01,148.35 ccw(c1022.01,134.35) 1008.01,134.35 1008.01,118.35 ccw(c1022.01,118.35) 1022.01,104.35 1070.01,104.35 ccw(c1070.01,111.41) 1077.07,111.41 1077.07,122.9 ccw(c1072.23,122.9) 1072.23,127.74 1065.18,127.74 cw(c1065.18,132.74) 1060.18,132.74 1060.18,139.95 cw(c1064.58,139.95) 1064.58,144.35 v3(1072.23,144.35)
  Layer 6 - Bottom Layer w7: v3(1072.23,144.35) J18.33@1072.23,185.61
CSI1_D2_N: J18.39 U1.40 | length 1699.9
  Layer 1 - Top Layer w7: U1.40@864.91,1481.42 v3(880.9,1465.43)
  Layer 3 - Sensitive w5: v3(880.9,1465.43) cw(c880.9,1448.9) 892.59,1460.59 909.87,1443.3 cw(c872.44,1405.87) 925.38,1405.87 925.38,499.74 cw(c917.26,499.74) 923,494 ccw(c937.49,479.51) 917,479.51 917,427 ccw(c955.97,427) 928.41,399.44 929.93,397.93 ccw(c949.07,417.07) 949.07,390 994.44,390 cw(c994.44,362.44) 1013.93,381.93 ccw(c1037.9,405.9) 1037.9,372 1103,372 cw(c1103,360) 1115,360 1115,359 cw(c1103,359) 1103,347 1095.38,347 ccw(c1095.38,304.69) 1065.46,334.61 ccw(c1081.07,319) 1059,319 1059,307.67 ccw(c1113.2,307.67) 1074.88,269.34 cw(c1042.63,237.1) 1088.23,237.1 1088.23,187.38 ccw(c1111.23,187.38) 1111.23,164.38 1127.51,164.38 ccw(c1127.51,183) 1146.13,183 1146.13,215.18 cw(c1162.66,215.18) v3(1150.97,226.87)
  Layer 6 - Bottom Layer w7: J18.39@1150.97,185.61 v3(1150.97,226.87)
CSI1_D2_P: J18.37 U1.41 | length 1697.8
  Layer 1 - Top Layer w7: U1.41@878.83,1495.34 v3(894.82,1479.35)
  Layer 3 - Sensitive w5: v3(894.82,1479.35) ccw(c911.35,1479.35) 899.65,1467.67 916.94,1450.38 cw(c872.44,1405.87) 935.38,1405.87 935.38,499.74 cw(c917.26,499.74) 930.07,486.93 ccw(c937.49,479.51) 927,479.51 927,427 ccw(c955.97,427) 935.49,406.51 937,405 ccw(c949.07,417.07) 949.07,400 994.44,400 cw(c994.44,362.44) 1021,389 ccw(c1037.9,405.9) 1037.9,382 1103,382 cw(c1103,360) 1125,360 1125,359 cw(c1103,359) 1103,337 1095.38,337 ccw(c1095.38,304.69) 1072.54,327.54 ccw(c1081.07,319) 1069,319 1069,307.67 ccw(c1113.2,307.67) 1081.95,276.42 cw(c1042.63,237.1) 1098.23,237.1 1098.23,187.38 ccw(c1111.23,187.38) 1111.23,174.38 1127.51,174.38 ccw(c1127.51,183) 1136.13,183 1136.13,205.42 ccw(c1131.29,205.42) 1131.29,210.26 1124.23,210.26 cw(c1124.23,215.26) 1119.23,215.26 1119.23,222.47 cw(c1123.63,222.47) 1123.63,226.87 v3(1131.28,226.87)
  Layer 6 - Bottom Layer w7: J18.37@1131.28,185.61 v3(1131.28,226.87)
CSI1_D3_N: J18.28 U1.42 | length 1699.6
  Layer 1 - Top Layer w7: U1.42@892.75,1509.26 v3(908.74,1493.28)
  Layer 3 - Sensitive w5: v3(908.74,1493.28) cw(c908.73,1476.74) 920.43,1488.43 940.39,1468.46 cw(c901.8,1429.87) 956.38,1429.87 956.38,611.62 ccw(c993,611.62) 993,575 1209,575 cw(c1209,554) 1230,554 1230,544 cw(c1209,544) 1209,523 1052,523 ccw(c1052,488) 1017,488 1017,445.56 cw(c1004,445.56) 1004,432.56 977.58,432.56 cw(c977.58,441.18) 968.96,441.18 968.96,448.33 cw(c973.8,448.33) 973.8,453.18 990,453.18 ccw(c990,458.18) 995,458.18 995,465.38 ccw(c990.6,465.38) 990.6,469.78 ; v3(973.8,469.78) 990,469.78
  Layer 6 - Bottom Layer w7: J18.28@973.8,428.52 v3(973.8,469.78)
CSI1_D3_P: J18.26 U1.43 | length 1698.7
  Layer 1 - Top Layer w7: U1.43@906.67,1523.18 v3(922.66,1507.2)
  Layer 3 - Sensitive w5: v3(922.66,1507.2) ccw(c939.19,1507.19) 927.49,1495.51 947.46,1475.53 cw(c901.8,1429.87) 966.38,1429.87 966.38,611.62 ccw(c993,611.62) 993,585 1209,585 cw(c1209,554) 1240,554 1240,544 cw(c1209,544) 1209,513 1052,513 ccw(c1052,488) 1027,488 1027,445.56 cw(c1004,445.56) 1004,422.56 977.58,422.56 cw(c977.58,441.18) 958.96,441.18 ; v3(954.12,469.78) cw(c942.43,458.09) 958.96,458.09 958.96,442.18
  Layer 6 - Bottom Layer w7: J18.26@954.12,428.52 v3(954.12,469.78)
DIAG_EN: R70.2 U10.14 U12.34 | length 2903.4
  Layer 1 - Top Layer w10: R70.2@185.38,5316.5 185.38,5245.62 v1(192,5239) 197,5234 197,5195.8 U10.14@199.66,5193.14 ; v1(1031.43,3241.14) U12.34@1031.43,3305.48
  Layer 3 - Sensitive w10: v1@191.5,5239.5 159,5207 159,5144 99,5084 99,4822 299.98,4621.02 659.38,4621.02 839.38,4441.02 839.38,3845.87 814.38,3820.87 814.38,3635.87 914.38,3535.87 1009.38,3535.87 1031.43,3513.82 v1(1031.43,3241.14)
EN_CAM1: R97.1 U10.3 | length 2751.3
  Layer 1 - Top Layer w10: U10.3@481,5193.3 v1(481,5246)
  Layer 3 - Sensitive w10: v1(481,5246) 592,5246 609,5229 609,5066.25 709.38,4965.87 709.38,4627.59 879.38,4457.59 879.38,3829.3 854.38,3804.3 854.38,3655.87 934.38,3575.87 1069.38,3575.87 1134.38,3510.87 1134.38,3445.87 1239.38,3340.87 v1(1239.38,3215.87)
  Layer 6 - Bottom Layer w10: R97.1@1159.38,3059.49 1159.38,3100.87 1239.38,3180.87 v1(1239.38,3215.87)
EN_CAM2: R100.1 U10.4 | length 2768.9
  Layer 1 - Top Layer w10: U10.4@456,5193.57 v1(456,5238)
  Layer 3 - Sensitive w10: v1(456,5238) 456,5261 465,5270 605,5270 633,5242 633,5072.25 729.38,4975.87 729.38,4635.87 899.38,4465.87 899.38,3785.87 959.38,3725.87 959.38,3625.87 989.38,3595.87 1079.38,3595.87 1154.38,3520.87 1154.38,3455.87 1264.38,3345.87 v1(1264.38,3240.87)
  Layer 6 - Bottom Layer w10: v1(1264.38,3240.87) 1264.38,3140.87 1294.38,3110.87 R100.1@1294.38,3059.49
EN_CAM3: R102.1 U10.5 | length 2407.3
  Layer 1 - Top Layer w10: U10.5@429.98,5193.14 429.98,5247.98 467,5285 552,5285 587,5250 587,5062 732,4917 v1(778,4917) ; R102.1@1183.62,3459.49 v1(1183.62,3490.87)
  Layer 3 - Sensitive w10: v1@778.25,4916.75 800,4895 800,4645.25 989.38,4455.87 1049.38,4455.87 1109.38,4395.87 1109.38,4207.59 1139.38,4177.59 1139.38,3815.87 1059.38,3735.87 1059.38,3645.87 1183.62,3521.63 v1(1183.62,3490.87)
EN_CAM4: R101.1 U10.6 | length 2433.4
  Layer 1 - Top Layer w10: U10.6@404.39,5193.14 404.39,5257.39 454,5307 572,5307 608,5271 608,5086 755,4939 v1(800,4939) ; R101.1@1228.62,3459.49 v1(1228.62,3490.87)
  Layer 3 - Sensitive w10: v1(800,4939) 825,4914 825,4655.25 999.38,4480.87 1059.38,4480.87 1129.38,4410.87 1129.38,4215.87 1159.38,4185.87 1159.38,3625.87 1228.62,3556.63 v1(1228.62,3490.87)
EXT_1V8: J13.3 J18.38 J18.40 | length 4856.6
  Layer 1 - Top Layer w30: v1(374.38,3635.87) 354.38,3655.87 354.38,3730.87 394.38,3770.87 514.38,3770.87 579.38,3835.87 J13.3@654.38,3835.87
  Layer 5 - PWR w30: v1(374.38,3635.87) 374.38,3401.38 284.38,3311.38 284.38,2915.87 339.38,2860.87 339.38,2830.87 364.38,2805.87 364.38,2571.38 72,2279 72,654 326.56,399.44 1157.44,399.44 v1(1172,414) v1(1172,439)
EXT_3V3: J9.3 J18.30 J18.32 J18.34 J18.36 | length 4981.7
  Layer 1 - Top Layer w30: v1(1082,1004) 1002,924 657,924 552,819 552,464 622,394 992,394 v1(1067,469) v1(1092,469)
  Layer 5 - PWR w30: J9.3@954.38,3835.87 1099.38,3835.87 1174.38,3760.87 1264.38,3760.87 1294.38,3730.87 1294.38,3375.87 1044.38,3125.87 1044.38,2660.87 1122,2583.25 1122,1959 1312,1769 1312,1234 v1(1082,1004)
EXT_VIN: J11.1 J21.1
FAULT_CAM: R76.2 U10.9 U12.33 | length 3057
  Layer 1 - Top Layer w10: U10.9@327.61,5193.14 327.61,5228.61 334,5235 v1(334,5256) ; v1(1057.02,3260.08) U12.33@1057.02,3305.48
  Layer 3 - Sensitive w10: v1@241,4735 241,4713 314,4640 668.68,4640 859.38,4449.3 859.38,3837.59 834.38,3812.59 834.38,3645.87 924.38,3555.87 1024.38,3555.87 1057.02,3523.23 v1(1057.02,3260.08)
  Layer 6 - Bottom Layer w10: v1(242,4736) 144.38,4736 R76.2@142,4733.62 142,5252 186,5296 294,5296 v1(334,5256)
